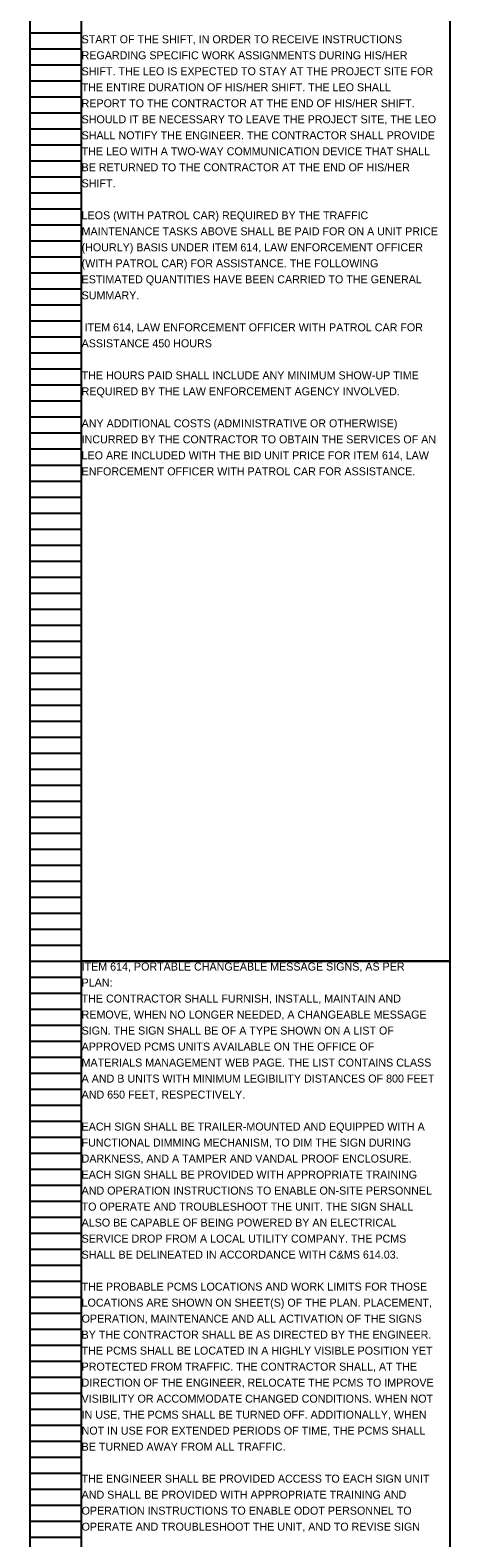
# Model space of a CAD drawing. Extents: x 16463 to 16500, y 5400 to 5823.
# Drawn here: x 16463.05 to 16470.39, y 5611.78 to 5638.16 of the extents above; entities that cross this region are included whole.
import ezdxf

# ---------------------------------------------------------------- set-up
doc = ezdxf.new("R2010")
doc.units = 0
for name, color, linetype in [('Default', 7, 'Continuous'), ('SC_Scratch1', 7, 'Continuous'), ('SH_Data', 7, 'Continuous')]:
    doc.layers.add(name, color=color, linetype=linetype)

msp = doc.modelspace()

# ---------------------------------------------------------------- linework, layer by layer
at = {"layer": 'SC_Scratch1'}
for points in [[(16463.949, 5642.032), (16470.389, 5642.032), (16470.389, 5621.872), (16463.949, 5621.872)], [(16463.949, 5621.872), (16470.389, 5621.872), (16470.389, 5601.712), (16463.949, 5601.712)]]:
    msp.add_lwpolyline(points, close=True, dxfattribs=at)
at = {"layer": 'SH_Data'}
for p, q in [((16463.049, 5621.872), (16463.049, 5642.032)), ((16463.949, 5621.872), (16463.949, 5642.032)), ((16463.049, 5638.112), (16463.949, 5638.112)), ((16463.049, 5637.832), (16463.949, 5637.832)), ((16463.049, 5637.552), (16463.949, 5637.552)), ((16463.049, 5637.272), (16463.949, 5637.272)), ((16463.049, 5636.992), (16463.949, 5636.992)), ((16463.049, 5636.712), (16463.949, 5636.712)), ((16463.049, 5636.432), (16463.949, 5636.432)), ((16463.049, 5636.152), (16463.949, 5636.152)), ((16463.049, 5635.872), (16463.949, 5635.872)), ((16463.049, 5635.592), (16463.949, 5635.592)), ((16463.049, 5635.312), (16463.949, 5635.312)), ((16463.049, 5635.032), (16463.949, 5635.032)), ((16463.049, 5634.752), (16463.949, 5634.752)), ((16463.049, 5634.472), (16463.949, 5634.472)), ((16463.049, 5634.192), (16463.949, 5634.192)), ((16463.049, 5633.912), (16463.949, 5633.912)), ((16463.049, 5633.632), (16463.949, 5633.632)), ((16463.049, 5633.352), (16463.949, 5633.352)), ((16463.049, 5633.072), (16463.949, 5633.072)), ((16463.049, 5632.792), (16463.949, 5632.792)), ((16463.049, 5632.512), (16463.949, 5632.512)), ((16463.049, 5632.232), (16463.949, 5632.232)), ((16463.049, 5631.952), (16463.949, 5631.952)), ((16463.049, 5631.672), (16463.949, 5631.672)), ((16463.049, 5631.392), (16463.949, 5631.392)), ((16463.049, 5631.112), (16463.949, 5631.112)), ((16463.049, 5630.832), (16463.949, 5630.832)), ((16463.049, 5630.552), (16463.949, 5630.552)), ((16463.049, 5630.272), (16463.949, 5630.272)), ((16463.049, 5629.992), (16463.949, 5629.992)), ((16463.049, 5629.712), (16463.949, 5629.712)), ((16463.049, 5629.432), (16463.949, 5629.432)), ((16463.049, 5629.152), (16463.949, 5629.152)), ((16463.049, 5628.872), (16463.949, 5628.872)), ((16463.049, 5628.592), (16463.949, 5628.592)), ((16463.049, 5628.312), (16463.949, 5628.312)), ((16463.049, 5628.032), (16463.949, 5628.032)), ((16463.049, 5627.752), (16463.949, 5627.752)), ((16463.049, 5627.472), (16463.949, 5627.472)), ((16463.049, 5627.192), (16463.949, 5627.192)), ((16463.049, 5626.912), (16463.949, 5626.912)), ((16463.049, 5626.632), (16463.949, 5626.632)), ((16463.049, 5626.352), (16463.949, 5626.352)), ((16463.049, 5626.072), (16463.949, 5626.072)), ((16463.049, 5625.792), (16463.949, 5625.792)), ((16463.049, 5625.512), (16463.949, 5625.512)), ((16463.049, 5625.232), (16463.949, 5625.232)), ((16463.049, 5624.952), (16463.949, 5624.952)), ((16463.049, 5624.672), (16463.949, 5624.672)), ((16463.049, 5624.392), (16463.949, 5624.392)), ((16463.049, 5624.112), (16463.949, 5624.112)), ((16463.049, 5623.832), (16463.949, 5623.832)), ((16463.049, 5623.552), (16463.949, 5623.552)), ((16463.049, 5623.272), (16463.949, 5623.272)), ((16463.049, 5622.992), (16463.949, 5622.992)), ((16463.049, 5622.712), (16463.949, 5622.712)), ((16463.049, 5622.432), (16463.949, 5622.432)), ((16463.049, 5622.152), (16463.949, 5622.152)), ((16463.049, 5601.712), (16463.049, 5621.872)), ((16463.049, 5621.872), (16463.949, 5621.872)), ((16463.049, 5621.872), (16463.949, 5621.872)), ((16463.949, 5601.712), (16463.949, 5621.872)), ((16463.049, 5621.592), (16463.949, 5621.592)), ((16463.049, 5621.312), (16463.949, 5621.312)), ((16463.049, 5621.032), (16463.949, 5621.032)), ((16463.049, 5620.752), (16463.949, 5620.752)), ((16463.049, 5620.472), (16463.949, 5620.472)), ((16463.049, 5620.192), (16463.949, 5620.192)), ((16463.049, 5619.912), (16463.949, 5619.912)), ((16463.049, 5619.632), (16463.949, 5619.632)), ((16463.049, 5619.352), (16463.949, 5619.352)), ((16463.049, 5619.072), (16463.949, 5619.072)), ((16463.049, 5618.792), (16463.949, 5618.792)), ((16463.049, 5618.512), (16463.949, 5618.512)), ((16463.049, 5618.232), (16463.949, 5618.232)), ((16463.049, 5617.952), (16463.949, 5617.952)), ((16463.049, 5617.672), (16463.949, 5617.672)), ((16463.049, 5617.392), (16463.949, 5617.392)), ((16463.049, 5617.112), (16463.949, 5617.112)), ((16463.049, 5616.832), (16463.949, 5616.832)), ((16463.049, 5616.552), (16463.949, 5616.552)), ((16463.049, 5616.272), (16463.949, 5616.272)), ((16463.049, 5615.992), (16463.949, 5615.992)), ((16463.049, 5615.712), (16463.949, 5615.712)), ((16463.049, 5615.432), (16463.949, 5615.432)), ((16463.049, 5615.152), (16463.949, 5615.152)), ((16463.049, 5614.872), (16463.949, 5614.872)), ((16463.049, 5614.592), (16463.949, 5614.592)), ((16463.049, 5614.312), (16463.949, 5614.312)), ((16463.049, 5614.032), (16463.949, 5614.032)), ((16463.049, 5613.752), (16463.949, 5613.752)), ((16463.049, 5613.472), (16463.949, 5613.472)), ((16463.049, 5613.192), (16463.949, 5613.192)), ((16463.049, 5612.912), (16463.949, 5612.912)), ((16463.049, 5612.632), (16463.949, 5612.632)), ((16463.049, 5612.352), (16463.949, 5612.352)), ((16463.049, 5612.072), (16463.949, 5612.072)), ((16463.049, 5611.792), (16463.949, 5611.792))]:
    msp.add_line(p, q, dxfattribs=at)

# ---------------------------------------------------------------- texts
at = {"layer": 'Default'}
for s, p in [('START OF THE SHIFT, IN ORDER TO RECEIVE INSTRUCTIONS ', (16463.949, 5637.931)), ('REGARDING SPECIFIC WORK ASSIGNMENTS DURING HIS/HER ', (16463.949, 5637.651)), ('SHIFT. THE LEO IS EXPECTED TO STAY AT THE PROJECT SITE FOR ', (16463.949, 5637.371)), ('THE ENTIRE DURATION OF HIS/HER SHIFT. THE LEO SHALL ', (16463.949, 5637.091)), ('REPORT TO THE CONTRACTOR AT THE END OF HIS/HER SHIFT. ', (16463.949, 5636.811)), ('SHOULD IT BE NECESSARY TO LEAVE THE PROJECT SITE, THE LEO ', (16463.949, 5636.531)), ('SHALL NOTIFY THE ENGINEER. THE CONTRACTOR SHALL PROVIDE ', (16463.949, 5636.251)), ('THE LEO WITH A TWO-WAY COMMUNICATION DEVICE THAT SHALL ', (16463.949, 5635.971)), ('BE RETURNED TO THE CONTRACTOR AT THE END OF HIS/HER ', (16463.949, 5635.691)), ('SHIFT.', (16463.949, 5635.411)), ('LEOS (WITH PATROL CAR) REQUIRED BY THE TRAFFIC ', (16463.949, 5634.851)), ('MAINTENANCE TASKS ABOVE SHALL BE PAID FOR ON A UNIT PRICE ', (16463.949, 5634.571)), ('(HOURLY) BASIS UNDER ITEM 614, LAW ENFORCEMENT OFFICER ', (16463.949, 5634.291)), ('(WITH PATROL CAR) FOR ASSISTANCE. THE FOLLOWING ', (16463.949, 5634.011)), ('ESTIMATED QUANTITIES HAVE BEEN CARRIED TO THE GENERAL ', (16463.949, 5633.731)), ('SUMMARY.', (16463.949, 5633.451)), (' ITEM 614, LAW ENFORCEMENT OFFICER WITH PATROL CAR FOR ', (16463.949, 5632.891)), ('ASSISTANCE 450 HOURS ', (16463.949, 5632.611)), ('THE HOURS PAID SHALL INCLUDE ANY MINIMUM SHOW-UP TIME ', (16463.949, 5632.051)), ('REQUIRED BY THE LAW ENFORCEMENT AGENCY INVOLVED. ', (16463.949, 5631.771)), ('ANY ADDITIONAL COSTS (ADMINISTRATIVE OR OTHERWISE) ', (16463.949, 5631.211)), ('INCURRED BY THE CONTRACTOR TO OBTAIN THE SERVICES OF AN ', (16463.949, 5630.931)), ('LEO ARE INCLUDED WITH THE BID UNIT PRICE FOR ITEM 614, LAW ', (16463.949, 5630.651)), ('ENFORCEMENT OFFICER WITH PATROL CAR FOR ASSISTANCE.', (16463.949, 5630.371)), ('ITEM 614, PORTABLE CHANGEABLE MESSAGE SIGNS, AS PER ', (16463.949, 5621.706)), ('PLAN:', (16463.949, 5621.426)), ('THE CONTRACTOR SHALL FURNISH, INSTALL, MAINTAIN AND ', (16463.949, 5621.146)), ('REMOVE, WHEN NO LONGER NEEDED, A CHANGEABLE MESSAGE ', (16463.949, 5620.866)), ('SIGN. THE SIGN SHALL BE OF A TYPE SHOWN ON A LIST OF ', (16463.949, 5620.586)), ('APPROVED PCMS UNITS AVAILABLE ON THE OFFICE OF ', (16463.949, 5620.306)), ('MATERIALS MANAGEMENT WEB PAGE. THE LIST CONTAINS CLASS ', (16463.949, 5620.026)), ('A AND B UNITS WITH MINIMUM LEGIBILITY DISTANCES OF 800 FEET ', (16463.949, 5619.746)), ('AND 650 FEET, RESPECTIVELY. ', (16463.949, 5619.466)), ('EACH SIGN SHALL BE TRAILER-MOUNTED AND EQUIPPED WITH A ', (16463.949, 5618.906)), ('FUNCTIONAL DIMMING MECHANISM, TO DIM THE SIGN DURING ', (16463.949, 5618.626)), ('DARKNESS, AND A TAMPER AND VANDAL PROOF ENCLOSURE. ', (16463.949, 5618.346)), ('EACH SIGN SHALL BE PROVIDED WITH APPROPRIATE TRAINING ', (16463.949, 5618.066)), ('AND OPERATION INSTRUCTIONS TO ENABLE ON-SITE PERSONNEL ', (16463.949, 5617.786)), ('TO OPERATE AND TROUBLESHOOT THE UNIT. THE SIGN SHALL ', (16463.949, 5617.506)), ('ALSO BE CAPABLE OF BEING POWERED BY AN ELECTRICAL ', (16463.949, 5617.226)), ('SERVICE DROP FROM A LOCAL UTILITY COMPANY. THE PCMS ', (16463.949, 5616.946)), ('SHALL BE DELINEATED IN ACCORDANCE WITH C&MS 614.03. ', (16463.949, 5616.666)), ('THE PROBABLE PCMS LOCATIONS AND WORK LIMITS FOR THOSE ', (16463.949, 5616.106)), ('LOCATIONS ARE SHOWN ON SHEET(S) OF THE PLAN. PLACEMENT, ', (16463.949, 5615.826)), ('OPERATION, MAINTENANCE AND ALL ACTIVATION OF THE SIGNS ', (16463.949, 5615.546)), ('BY THE CONTRACTOR SHALL BE AS DIRECTED BY THE ENGINEER. ', (16463.949, 5615.266)), ('THE PCMS SHALL BE LOCATED IN A HIGHLY VISIBLE POSITION YET ', (16463.949, 5614.986)), ('PROTECTED FROM TRAFFIC. THE CONTRACTOR SHALL, AT THE ', (16463.949, 5614.706)), ('DIRECTION OF THE ENGINEER, RELOCATE THE PCMS TO IMPROVE ', (16463.949, 5614.426)), ('VISIBILITY OR ACCOMMODATE CHANGED CONDITIONS. WHEN NOT ', (16463.949, 5614.146)), ('IN USE, THE PCMS SHALL BE TURNED OFF. ADDITIONALLY, WHEN ', (16463.949, 5613.866)), ('NOT IN USE FOR EXTENDED PERIODS OF TIME, THE PCMS SHALL ', (16463.949, 5613.586)), ('BE TURNED AWAY FROM ALL TRAFFIC. ', (16463.949, 5613.306)), ('THE ENGINEER SHALL BE PROVIDED ACCESS TO EACH SIGN UNIT ', (16463.949, 5612.746)), ('AND SHALL BE PROVIDED WITH APPROPRIATE TRAINING AND ', (16463.949, 5612.466)), ('OPERATION INSTRUCTIONS TO ENABLE ODOT PERSONNEL TO ', (16463.949, 5612.186)), ('OPERATE AND TROUBLESHOOT THE UNIT, AND TO REVISE SIGN ', (16463.949, 5611.906))]:
    msp.add_text(s, height=0.14, dxfattribs=at).set_placement(p)

doc.saveas('drawing.dxf')
